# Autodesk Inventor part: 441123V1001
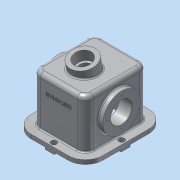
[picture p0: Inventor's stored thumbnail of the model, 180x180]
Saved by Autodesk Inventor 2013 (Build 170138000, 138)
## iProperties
Created: 2014-11
Part Number: 441123V1001
Material: 알루미늄 6061
Document SubType Name: Modeling
Designer: WINDOWS7
Density: 1 g/cm^3
Author: WINDOWS7
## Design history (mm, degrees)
sketch "스케치1"
  geometry: L1 (0, 0)-(130, 0); L2 (130, 0)-(130, 152); L3 (130, 152)-(0, 152); L4 (0, 152)-(0, 0)
  constraints: 8 end point, 2 parallel, 1 horizontal, 1 perpendicular
  dimensions: "d0" = 130 distance of L1.start L1.end; "d1" = 152 distance of L3.end L1.start
extrude "돌출1" new body sketch "스케치1" distance "d2" = 118; taper "d3" = 0 deg
feature "쉘1" dims "d4" = 10
fillet "모깎기1" dims "d5" = 20
fillet "모깎기2" dims "d6" = 10
sketch "스케치2"
  geometry: L1 (-20, 10)-(-110, 10) reference; L2 (-120, 20)-(-120, 132) reference; L3 (-110, 142)-(-20, 142) reference; L4 (-10, 132)-(-10, 20) reference; L5 (-110, 152)-(-20, 152) reference; L6 (-130, 20)-(-130, 132) reference; L7 (22, 174)-(-152, 174); L8 (-152, 174)-(-152, -22); L9 (-152, -22)-(22, -22); L10 (22, -22)-(22, 174); A1 r 10 centre (-110, 20) between (-120, 20) and (-110, 10) reference; A2 r 10 centre (-110, 132) between (-110, 142) and (-120, 132) reference; A3 r 10 centre (-20, 132) between (-10, 132) and (-20, 142) reference; A4 r 10 centre (-20, 20) between (-20, 10) and (-10, 20) reference; 5 further points
  constraints: 8 end point, 4 midpoint, 2 parallel, 1 horizontal, 1 horizontal alignment, 1 perpendicular, 1 vertical alignment
  dimensions: "d7" = 174 distance between parallel lines of L8 L10; "d9" = 196 distance between parallel lines of L7 L9
extrude "돌출2" join sketch "스케치2" distance "d10" = 10; taper "d11" = 0 deg
fillet "모깎기3" dims "d12" = 10
fillet "모깎기4" dims "d13" = 42
sketch "스케치3"
  geometry: L1 (-20, 174)-(-110, 174) reference; L2 (-152, 132)-(-152, 20) reference; L3 (-110, -22)-(-20, -22) reference; L4 (-152, 87)-(-132, 87); L5 (-132, 87)-(-132, 65); L6 (-132, 65)-(-152, 65); L7 (-152, 65)-(-152, 87); L8 (-76, 174)-(-54, 174); L9 (-54, 174)-(-54, 154); L10 (-54, 154)-(-76, 154); L11 (-76, 154)-(-76, 174); 6 further points
  constraints: 16 end point, 6 midpoint, 4 parallel, 2 coincident, 2 horizontal, 2 perpendicular, 1 point on line
  dimensions: "d14" = 20 distance of L5.end L6.end; "d16" = 22 distance of L4.end L5.end; "d20" = 20 distance of L10.end L8.start; "d21" = 22 distance of L9.end L10.end
extrude "돌출3" join sketch "스케치3" distance "d22" = 5; taper "d23" = 0 deg
node "작업 평면1"
node "작업 평면2"
sketch "스케치4"
  geometry: L1 (0, 108)-(90, 108) reference; L2 (34, -10)-(0, -10) reference; 3 further points
  constraints: 1 midpoint, 1 vertical alignment, 1 other
  dimensions: "d24" = 92 distance from line of point (45, 82) L2
feature "엠보싱1" sketch "스케치4" dims "d25" = 1, "d26" = 0
node "작업 평면3"
node "작업 평면4"
sketch "스케치5"
  geometry: L1 (-20, 0)-(-20, 108) reference; L2 (-10, 108)-(-10, -10) reference; L3 (100, -10)-(100, 108) reference; L4 (110, 108)-(110, 0) reference; L5 (-20, 58)-(110, 58); L6 (90, -10)-(0, -10) reference; L7 (-20, 84)-(-32, 84); L8 (-32, 84)-(-32, 103.5); L9 (-32, 103.5)-(-20, 103.5); L10 (-20, 103.5)-(-10, 103.5); L11 (-10, 103.5)-(0, 93.5); L12 (0, 93.5)-(0, 84); L13 (0, 84)-(-20, 84); L14 (45, 58)-(45, -10)
  constraints: 18 end point, 6 perpendicular, 5 point on line, 2 midpoint, 1 parallel
  dimensions: "d27" = 68 distance between parallel lines of L6 L5; "d28" = 32 distance between parallel lines of L12 L8; "d30" = 52 diameter of L13 L5; "d31" = 91 diameter of L9 L5; "d32" = 71 diameter of L11.end L5; "d83" = 10 horizontal distance of L10.end L11.end
revolve "회전1" sketch "스케치5" stored, may be unused: angle "d33" = 90 deg
node "작업 평면5"
sketch "스케치6"
  geometry: C1 r 26 at (0, 0) reference; 1 further point
extrude "돌출4" cut sketch "스케치6" distance "d34" = 322; taper "d35" = 0 deg
node "작업 평면6"
sketch "스케치7"
  geometry: L1 (58, 56)-(169.222, 32.359); L2 (0, 0)-(0, -42) reference; L3 (142.121, 38.12)-(135.675, 7.797); L4 (135.675, 7.797)-(51.555, 25.677); L5 (51.555, 25.677)-(58, 56); C1 r 26 at (58, 56) reference; 1 further point
  constraints: 8 end point, 2 perpendicular, 1 point on line
  dimensions: "d36" = 78 deg angle of L2 L1; "d37" = 86 distance from line of L1.start L3; "d39" = 62 diameter of L4 L1
revolve "회전2" sketch "스케치7" stored, may be unused: angle "d40" = 90 deg
sketch "스케치8"
  geometry: L1 (90, 0)-(0, 0) reference; L2 (0, 132)-(90, 132) reference; L3 (0, 101.5)-(0, 30.5) reference; L4 (-10, 111.5)-(-10, 20.5) reference; L5 (90, 101.5)-(90, 30.5) reference; L6 (100, 20.5)-(100, 111.5) reference; L7 (0, 101.5)-(0, 132); L8 (0, 30.5)-(0, 0); L9 (90, 30.5)-(90, 0); L10 (0, 0)-(90, 0); L11 (90, 30.5)-(90, 132); L12 (90, 132)-(0, 132); L13 (0, 101.5)-(0, 30.5); A1 r 10 centre (0, 122) between (0, 132) and (-10, 122) reference; A2 r 10 centre (0, 10) between (-10, 10) and (0, 0) reference; A3 r 10 centre (90, 10) between (90, 0) and (100, 10) reference; A4 r 10 centre (90, 122) between (100, 122) and (90, 132) reference; 1 further point
  constraints: 14 end point, 4 collinear, 4 tangent, 2 parallel, 1 perpendicular
extrude "돌출5" cut sketch "스케치8" distance "d41" = 322; taper "d42" = 0 deg
hole "구멍1" diameter "d45" = 30; stored, may be unused: countersink angle "d49" = 90 deg, drill point angle "d51" = 118 deg; dims "d43" = 10, "d44" = 10, "d46" = 6, "d47" = 42, "d48" = 25, "d50" = 45
sketch "스케치9"
  geometry: L1 (-22, 20)-(-22, 132) reference; L2 (110, -22)-(20, -22) reference; L3 (152, 132)-(152, 20) reference; L4 (20, 174)-(110, 174) reference; L5 (0, 132)-(0, 20) reference; L6 (110, 152)-(20, 152) reference; L7 (65, 164)-(65, -12); 10 further points
  constraints: 6 midpoint, 3 horizontal alignment, 3 vertical alignment, 2 end point, 1 perpendicular
  dimensions: "d54" = 10 distance from line of L1 point (-12, 76); "d55" = 10 distance from line of L3 point (142, 76); "d56" = 176 distance of L7.end L7.start
hole "구멍2" sketch "스케치9" at (-12, 76), (142, 76), (65, -12), (65, 164) diameter "d57" = 9; stored, may be unused: countersink angle "d61" = 90 deg, drill point angle "d63" = 118 deg; dims "d58" = 6, "d59" = 14, "d60" = 8.6, "d62" = 45
fillet "모깎기5" dims "d64" = 3
fillet "모깎기6" dims "d65" = 3
fillet "모깎기7" dims "d66" = 3
fillet "모깎기8" dims "d67" = 0.3
chamfer "모따기1" distance "d68" = 1; stored, may be unused: second distance "d69" = 2, angle "d70" = 45 deg
sketch "스케치10" dims "d71" = 70
  geometry: C1 r 45.5 at (0, 0) reference; C2 r 27 at (0, 0) reference; 3 further points
  constraints: 2 horizontal alignment, 1 coincident, 2 other
hole "구멍3" sketch "스케치10" at (-35, 0) diameter "d73" = 3.242; stored, may be unused: countersink angle "d77" = 90 deg, drill point angle "d79" = 118 deg; dims "d74" = 13, "d75" = 14, "d76" = 8.6, "d78" = 16
node "작업 평면7"
node "솔리드1"
mirror "대칭1"
mirror "대칭2"
mirror "대칭3"
pattern_circular "원형 패턴1" dims angle "d81" = 360 deg
mirror "대칭4"
node "투영된 루프1"
node "투영된 루프2"
